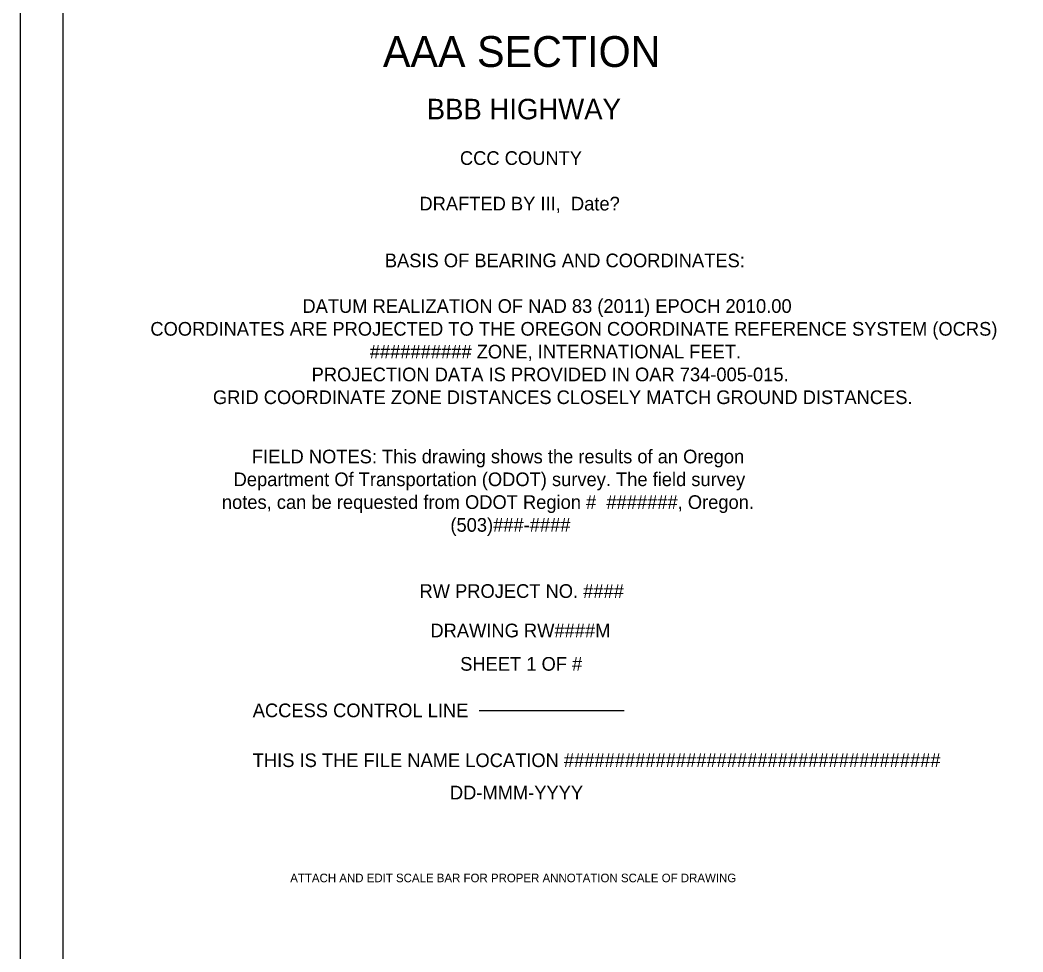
# Model space of a CAD drawing. Extents: x -1.2 to 17.3, y -1 to 2.5.
# Drawn here: x 0 to 0.975, y 0.739 to 1.645 of the extents above; entities that cross this region are included whole.
import ezdxf

# ---------------------------------------------------------------- set-up
doc = ezdxf.new("R2010")
doc.units = 0
for name, color, linetype in [('#plot_shape', 7, 'Continuous'), ('Default', 7, 'Continuous'), ('P_ODOT_PLAN_Border', 7, 'Continuous'), ('P_ODOT_PLAN_General', 7, 'Continuous')]:
    doc.layers.add(name, color=color, linetype=linetype)

msp = doc.modelspace()

# ---------------------------------------------------------------- linework, layer by layer
at = {"layer": '#plot_shape'}
msp.add_lwpolyline([(0, 0), (16.66667, 0), (16.66667, 2), (0, 2)], close=True, dxfattribs=at)
msp.add_lwpolyline([(0, 0), (16.66667, 0), (16.66667, 2), (0, 2)], close=True, dxfattribs=at)
at = {"layer": 'P_ODOT_PLAN_Border'}
msp.add_lwpolyline([(0.04167, 0.04167), (16.625, 0.04167), (16.625, 1.95833), (0.04167, 1.95833)], close=True, dxfattribs=at)
msp.add_lwpolyline([(0.04167, 0.04167), (16.625, 0.04167), (16.625, 1.95833), (0.04167, 1.95833)], close=True, dxfattribs=at)
at = {"layer": 'P_ODOT_PLAN_General'}
msp.add_lwpolyline([(0.44617, 0.97422), (0.587, 0.97422)], dxfattribs=at)
msp.add_lwpolyline([(0.44617, 0.97422), (0.587, 0.97422)], dxfattribs=at)
msp.add_lwpolyline([(0.44617, 0.97422), (0.587, 0.97422)], dxfattribs=at)
msp.add_lwpolyline([(0.44617, 0.97422), (0.587, 0.97422)], dxfattribs=at)

# ---------------------------------------------------------------- texts
at = {"layer": 'Default'}
msp.add_text('THIS IS THE FILE NAME LOCATION #####################################', height=0.0133, dxfattribs=at).set_placement((0.22611, 0.91907))
msp.add_text('THIS IS THE FILE NAME LOCATION #####################################', height=0.0133, dxfattribs=at).set_placement((0.22611, 0.91907))
at = {"layer": 'P_ODOT_PLAN_General'}
for s, height, p in [('AAA SECTION', 0.03, (0.35262, 1.5998)), ('AAA SECTION', 0.03, (0.35262, 1.5998)), ('BBB HIGHWAY', 0.02, (0.39516, 1.54882)), ('BBB HIGHWAY', 0.02, (0.39516, 1.54882)), ('CCC COUNTY', 0.0133, (0.42746, 1.50456)), ('CCC COUNTY', 0.0133, (0.42746, 1.50456)), ('DRAFTED BY III,  Date?', 0.0133, (0.3881, 1.46028)), ('DRAFTED BY III,  Date?', 0.0133, (0.3881, 1.46028)), ('BASIS OF BEARING AND COORDINATES:', 0.0133, (0.35448, 1.40502)), ('BASIS OF BEARING AND COORDINATES:', 0.0133, (0.35448, 1.40502)), ('DATUM REALIZATION OF NAD 83 (2011) EPOCH 2010.00  ', 0.0133, (0.27439, 1.36069)), ('DATUM REALIZATION OF NAD 83 (2011) EPOCH 2010.00  ', 0.0133, (0.27439, 1.36069)), ('COORDINATES ARE PROJECTED TO THE OREGON COORDINATE REFERENCE SYSTEM (OCRS) ', 0.0133, (0.12664, 1.33852)), ('COORDINATES ARE PROJECTED TO THE OREGON COORDINATE REFERENCE SYSTEM (OCRS) ', 0.0133, (0.12664, 1.33852)), (' ########## ZONE, INTERNATIONAL FEET.', 0.0133, (0.33494, 1.31636)), (' ########## ZONE, INTERNATIONAL FEET.', 0.0133, (0.33494, 1.31636)), ('PROJECTION DATA IS PROVIDED IN OAR 734-005-015.', 0.0133, (0.28334, 1.29419)), ('PROJECTION DATA IS PROVIDED IN OAR 734-005-015.', 0.0133, (0.28334, 1.29419)), ('GRID COORDINATE ZONE DISTANCES CLOSELY MATCH GROUND DISTANCES.', 0.0133, (0.18743, 1.27202)), ('GRID COORDINATE ZONE DISTANCES CLOSELY MATCH GROUND DISTANCES.', 0.0133, (0.18743, 1.27202)), ('FIELD NOTES: This drawing shows the results of an Oregon', 0.0133, (0.22527, 1.21439)), ('FIELD NOTES: This drawing shows the results of an Oregon', 0.0133, (0.22527, 1.21439)), ('Department Of Transportation (ODOT) survey. The field survey', 0.0133, (0.20752, 1.19222)), ('Department Of Transportation (ODOT) survey. The field survey', 0.0133, (0.20752, 1.19222)), ('notes, can be requested from ODOT Region #  #######, Oregon.', 0.0133, (0.19612, 1.17005)), ('notes, can be requested from ODOT Region #  #######, Oregon.', 0.0133, (0.19612, 1.17005)), ('(503)###-####', 0.0133, (0.41818, 1.14789)), ('(503)###-####', 0.0133, (0.41818, 1.14789)), ('RW PROJECT NO. ####', 0.0133, (0.38815, 1.08359)), ('RW PROJECT NO. ####', 0.0133, (0.38815, 1.08359)), ('DRAWING RW####M', 0.0133, (0.39877, 1.04522)), ('DRAWING RW####M', 0.0133, (0.39877, 1.04522)), ('SHEET 1 OF #', 0.0133, (0.4277, 1.01277)), ('SHEET 1 OF #', 0.0133, (0.4277, 1.01277)), ('ACCESS CONTROL LINE', 0.0133, (0.22611, 0.96757)), ('ACCESS CONTROL LINE', 0.0133, (0.22611, 0.96757)), ('DD-MMM-YYYY', 0.0133, (0.41772, 0.88764)), ('DD-MMM-YYYY', 0.0133, (0.41772, 0.88764)), ('ATTACH AND EDIT SCALE BAR FOR PROPER ANNOTATION SCALE OF DRAWING', 0.008333, (0.26255, 0.8071)), ('ATTACH AND EDIT SCALE BAR FOR PROPER ANNOTATION SCALE OF DRAWING', 0.008333, (0.26255, 0.8071))]:
    msp.add_text(s, height=height, dxfattribs=at).set_placement(p)

doc.saveas('drawing.dxf')
